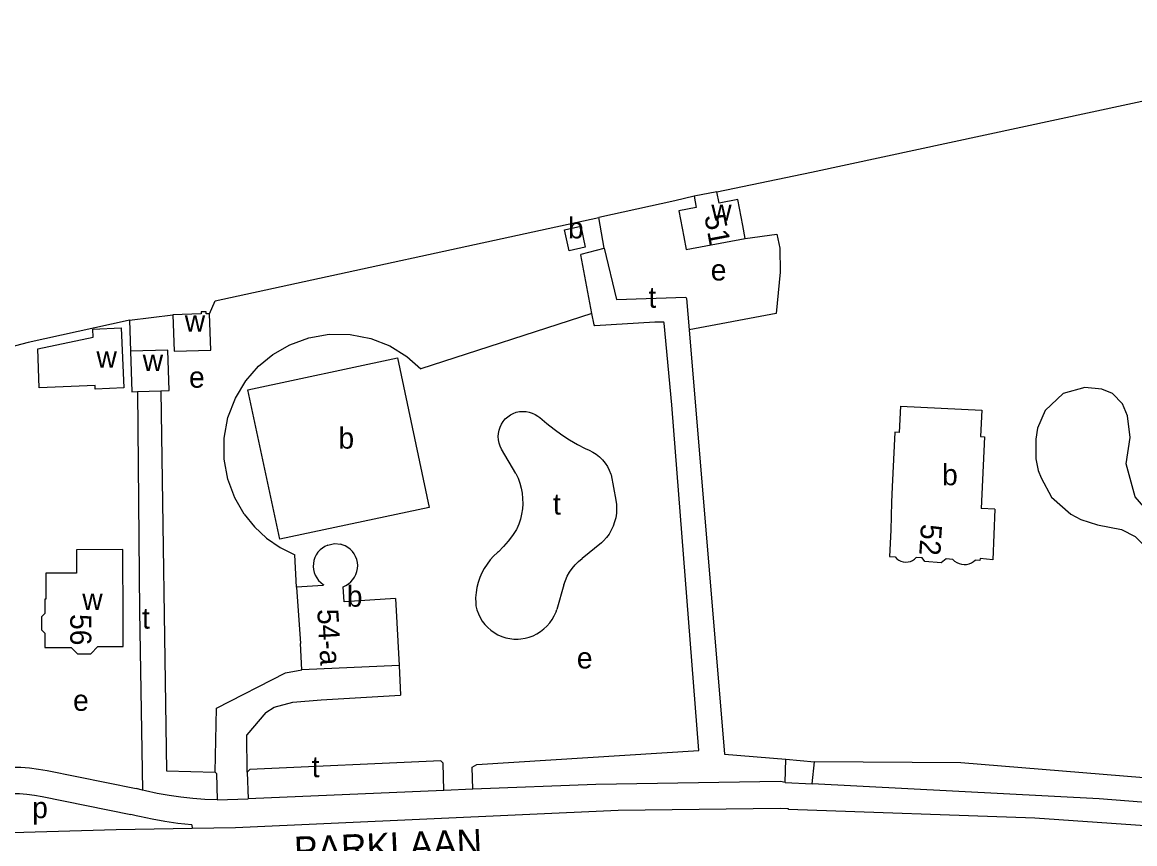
# Model space of a CAD drawing. Extents: x 161775 to 163181, y 382878 to 383925.
# Drawn here: x 161952.3 to 162163.3, y 383621.1 to 383777 of the extents above; entities that cross this region are included whole.
import ezdxf

# ---------------------------------------------------------------- set-up
doc = ezdxf.new("R2010")
doc.units = 0
for name, color, linetype in [('BLT_Basislijn', 7, 'Continuous'), ('BLT_Bebouwing', 7, 'Continuous'), ('BLT_Centroide', 7, 'Continuous'), ('BLT_Huisnummer', 7, 'Continuous'), ('BLT_Huisnummer_reeks', 7, 'Continuous'), ('BLT_Straatnaam', 7, 'Continuous')]:
    doc.layers.add(name, color=color, linetype=linetype)

msp = doc.modelspace()

# ---------------------------------------------------------------- linework, layer by layer
at = {"layer": 'BLT_Basislijn'}
for p, q in [((162084.08, 383744.78), (162102.02, 383748.52)), ((162062.72, 383734.11), (162061.69, 383739.92)), ((161972.7, 383720.42), (161980.91, 383721.44)), ((161972.7, 383720.42), (161972.84, 383714.54)), ((162060.39, 383721.72), (162027.96, 383711.22)), ((162095.3, 383721.67), (162078.84, 383718.61)), ((162045.97, 383691.34), (162043.25, 383695.99)), ((162064.01, 383691.09), (162064.93, 383686.3)), ((162062.18, 383678.16), (162058.52, 383675.21)), ((162004.33, 383669.8), (162004.01, 383675.93)), ((162055.06, 383670.23), (162053.74, 383665.54)), ((162023.8, 383654.88), (162024.05, 383649.27)), ((162000.09, 383647.01), (162003.63, 383647.96)), ((162003.63, 383647.96), (162009.02, 383648.4)), ((162009.02, 383648.4), (162024.05, 383649.27)), ((161998.54, 383645.99), (161994.94, 383641.76)), ((161998.54, 383645.99), (162000.09, 383647.01)), ((161995, 383634.68), (161994.94, 383641.76)), ((162097.05, 383632.73), (162097.18, 383637.12)), ((162097.18, 383637.12), (162102.58, 383636.62)), ((162102.16, 383632.48), (162102.58, 383636.62)), ((161957.05, 383634.98), (161973.91, 383631.58)), ((161975.16, 383631.26), (161973.91, 383631.58)), ((162032.32, 383631.2), (161995.16, 383629.58)), ((162037.8, 383631.47), (162032.32, 383631.2)), ((162097.05, 383632.73), (162102.16, 383632.48)), ((161956.13, 383630.06), (161972.92, 383626.67)), ((161989.27, 383629.43), (161995.16, 383629.58)), ((161973.96, 383626.41), (161972.92, 383626.67)), ((161984.52, 383624.67), (161984.53, 383623.99))]:
    msp.add_line(p, q, dxfattribs=at)
for points in [[(162102.02, 383748.52), (162181.43, 383765.6), (162207.15, 383772.92), (162219.96, 383776.97)], [(162079.78, 383743.97), (162076.13, 383743.06), (162061.69, 383739.92)], [(161987.86, 383721.65), (161988.93, 383724.12), (162061.69, 383739.92)], [(162089.44, 383735.94), (162095.45, 383736.78), (162096.04, 383734.08), (162096.08, 383729.57), (162095.3, 383721.67)], [(162060.39, 383721.72), (162058.3, 383732.81), (162058.35, 383732.97), (162062.72, 383734.11)], [(162062.72, 383734.11), (162065.06, 383724.33), (162078.19, 383724.78), (162078.35, 383724.56), (162078.84, 383718.61)], [(161972.7, 383720.42), (161972.4, 383720.39), (161953.48, 383716.22), (161914.12, 383705.92), (161900, 383701.78), (161882.86, 383696.55)], [(162037.8, 383631.47), (162037.69, 383635.6), (162038.53, 383636.13), (162080.66, 383638.81), (162075.54, 383704.37), (162074.08, 383719.89), (162074.01, 383720.08), (162072.29, 383720.08), (162060.96, 383719.38), (162060.8, 383719.54), (162060.39, 383721.72)], [(161994.43, 383683.62), (161992.64, 383686.71), (161991.33, 383690.24), (161990.62, 383694.07), (161990.62, 383698.05), (161991.35, 383701.97), (161992.76, 383705.66), (161994.74, 383708.94), (161997.16, 383711.7), (161999.88, 383713.94), (162003.06, 383715.78), (162006.66, 383717.09), (162010.54, 383717.77), (162014.54, 383717.73), (162018.44, 383716.96), (162022.06, 383715.54), (162025.27, 383713.57), (162027.96, 383711.22)], [(162078.84, 383718.61), (162085.51, 383638.09), (162097.18, 383637.12)], [(161978.59, 383707.03), (161979.67, 383634.9), (161988.89, 383634.7)], [(162169.13, 383680.34), (162163.39, 383686.91), (162161.7, 383693.18), (162162.49, 383698.2), (162161.98, 383702.31), (162161, 383704.58), (162159.09, 383706.49), (162157.08, 383707.35), (162153.9, 383707.67), (162149.76, 383706.55), (162146.32, 383703.31), (162144.87, 383699.97), (162144.59, 383697.88), (162144.59, 383694.14), (162145.03, 383691.88), (162145.56, 383690.51), (162147.53, 383686.82), (162151.19, 383683.64), (162153.1, 383682.64), (162156.29, 383681.62), (162160.84, 383680.7), (162163.39, 383679.4), (162165.31, 383677.52), (162166.85, 383674.82)], [(161974.19, 383706.88), (161974.54, 383665.2), (161975.16, 383631.26)], [(162043.25, 383695.99), (162042.98, 383696.54), (162042.77, 383697.12), (162042.65, 383697.73), (162042.61, 383698.34), (162042.64, 383698.96), (162042.76, 383699.56), (162042.95, 383700.15), (162043.21, 383700.7), (162043.55, 383701.22), (162043.95, 383701.69), (162044.41, 383702.1), (162044.92, 383702.46), (162045.46, 383702.74), (162046.04, 383702.95), (162046.65, 383703.08), (162047.26, 383703.13), (162047.88, 383703.11), (162048.49, 383703), (162049.07, 383702.82), (162049.63, 383702.56), (162050.15, 383702.23), (162050.48, 383701.97)], [(162050.48, 383701.97), (162051.82, 383700.82), (162053.21, 383699.73), (162054.65, 383698.7), (162056.13, 383697.74), (162057.66, 383696.85), (162059.13, 383696.07)], [(162059.13, 383696.07), (162059.86, 383695.78), (162060.56, 383695.42), (162061.21, 383694.99), (162061.82, 383694.49), (162062.38, 383693.94), (162062.87, 383693.33), (162063.31, 383692.67), (162063.67, 383691.98), (162063.96, 383691.24), (162064.01, 383691.09)], [(162045.97, 383691.34), (162046.38, 383690.44), (162046.71, 383689.51), (162046.96, 383688.55), (162047.14, 383687.58), (162047.24, 383686.6), (162047.25, 383685.61), (162047.19, 383684.62), (162047.05, 383683.64), (162046.83, 383682.68), (162046.53, 383681.74), (162046.16, 383680.82), (162046.1, 383680.71)], [(162064.93, 383686.3), (162065.04, 383685.47), (162065.07, 383684.63), (162065.02, 383683.79), (162064.9, 383682.95), (162064.69, 383682.14), (162064.41, 383681.35), (162064.05, 383680.58), (162063.62, 383679.86), (162063.13, 383679.17), (162062.57, 383678.54), (162062.18, 383678.16)], [(161994.43, 383683.62), (161996.38, 383681.21), (161998.67, 383679.08), (162001.24, 383677.31), (162004.01, 383675.93)], [(162046.1, 383680.71), (162045.33, 383679.58), (162044.49, 383678.51), (162043.59, 383677.48), (162042.63, 383676.51), (162042.44, 383676.33)], [(162042.44, 383676.33), (162041.73, 383675.66), (162041.08, 383674.94), (162040.48, 383674.16), (162039.96, 383673.34), (162039.5, 383672.48), (162039.11, 383671.58), (162038.8, 383670.65), (162038.57, 383669.7), (162038.41, 383668.74), (162038.33, 383667.77), (162038.34, 383666.79), (162038.37, 383666.26)], [(162055.06, 383670.23), (162055.34, 383671.05), (162055.7, 383671.85), (162056.13, 383672.61), (162056.63, 383673.34), (162057.19, 383674.01), (162057.81, 383674.63), (162058.52, 383675.21)], [(162168.35, 383672.76), (162173.38, 383669.31), (162180.96, 383669.11), (162183.12, 383666.7), (162182.8, 383632.96), (162182.64, 383632.33), (162180.48, 383632.31), (162130.35, 383636.45), (162102.58, 383636.62)], [(162038.37, 383666.26), (162038.56, 383665.49), (162038.84, 383664.74), (162039.18, 383664.02), (162039.59, 383663.35), (162040.08, 383662.71), (162040.62, 383662.13), (162041.21, 383661.61), (162041.86, 383661.15), (162042.55, 383660.76), (162043.28, 383660.43), (162044.03, 383660.18), (162044.81, 383660.02), (162045.6, 383659.92), (162046.39, 383659.91), (162046.92, 383659.95)], [(162046.92, 383659.95), (162047.71, 383660.08), (162048.49, 383660.28), (162049.24, 383660.56), (162049.96, 383660.92), (162050.64, 383661.34), (162051.28, 383661.84), (162051.86, 383662.39), (162052.39, 383662.99), (162052.85, 383663.65), (162053.25, 383664.35), (162053.58, 383665.09), (162053.74, 383665.54)], [(161988.89, 383634.7), (161989.15, 383646.84), (162002.26, 383653.54), (162005.37, 383654.06)], [(161950.34, 383635.64), (161952.05, 383635.59), (161953.72, 383635.47), (161955.39, 383635.26), (161957.05, 383634.98)], [(162032.32, 383631.2), (162032.15, 383636.37), (162031.74, 383636.8), (161995.48, 383635.18), (161995, 383634.68)], [(161988.89, 383634.7), (161989.15, 383634.43), (161989.27, 383629.43)], [(161995, 383634.68), (161995.16, 383629.58)], [(161989.27, 383629.43), (161986.98, 383629.51), (161984.7, 383629.68), (161982.43, 383629.93), (161980.17, 383630.25), (161977.92, 383630.65), (161975.68, 383631.13), (161975.16, 383631.26)], [(162097.05, 383632.73), (162096.16, 383632.87), (162061.12, 383632.31), (162037.8, 383631.47)], [(162187.15, 383627.23), (162156.61, 383629.61), (162102.16, 383632.48)], [(161950.21, 383630.64), (161951.79, 383630.6), (161953.23, 383630.49), (161954.66, 383630.32), (161956.13, 383630.06)], [(162190.28, 383626.87), (162185.31, 383623.07), (162144.41, 383625.95), (162097.66, 383627.58), (162097.66, 383627.74), (162096.06, 383627.77), (162065.35, 383627.38), (161992.75, 383624.13)], [(161984.52, 383624.67), (161981.81, 383624.96), (161979.37, 383625.31), (161976.95, 383625.75), (161974.55, 383626.26), (161973.96, 383626.41)], [(161984.53, 383623.99), (161970.12, 383623.75), (161950.39, 383623.19)], [(161992.75, 383624.13), (161984.53, 383623.99)]]:
    msp.add_lwpolyline(points, dxfattribs=at)
at = {"layer": 'BLT_Bebouwing'}
for p, q in [((162084.08, 383744.78), (162079.78, 383743.97)), ((161974.19, 383706.88), (161978.59, 383707.03)), ((162136.8, 383684.56), (162134.2, 383684.69)), ((162009.45, 383670.26), (162009.38, 383670.08)), ((162023.11, 383667.63), (162023.8, 383654.88))]:
    msp.add_line(p, q, dxfattribs=at)
for points in [[(162079.78, 383743.97), (162080.18, 383741.83), (162076.86, 383741.21), (162077.79, 383736.24), (162078.24, 383733.84), (162089.44, 383735.94)], [(162089.44, 383735.94), (162088.98, 383738.4), (162088.06, 383743.31), (162084.49, 383742.64), (162084.08, 383744.78)], [(162055.21, 383737.6), (162058.26, 383738.28), (162059.12, 383734.27), (162056.08, 383733.59), (162055.21, 383737.6)], [(161987.86, 383721.65), (161987.2, 383721.62), (161987.19, 383722.03), (161986.25, 383721.99), (161986.27, 383721.61), (161980.91, 383721.44)], [(161980.91, 383721.44), (161981.14, 383714.53)], [(161981.14, 383714.53), (161988.08, 383714.76), (161987.86, 383721.65)], [(161979.93, 383714.77), (161972.84, 383714.54)], [(161972.84, 383714.54), (161973.09, 383706.85), (161974.19, 383706.88)], [(161978.59, 383707.03), (161980.18, 383707.08), (161979.93, 383714.77)], [(161995.12, 383707.23), (162023.48, 383713.26), (162029.5, 383684.91), (162001.16, 383678.88), (161995.12, 383707.23)], [(162118.88, 383704.11), (162118.64, 383699.12), (162117.84, 383699.16), (162117.33, 383688.84), (162117.19, 383685.91), (162117.05, 383680.61), (162116.8, 383675.61), (162117.9, 383675.52)], [(162118.88, 383704.11), (162134.31, 383703.36), (162134.07, 383698.36), (162134.87, 383698.33), (162134.2, 383684.69)], [(162136.8, 383684.56), (162136.42, 383674.98), (162134.01, 383675.19), (162133.98, 383674.83), (162133.09, 383674.91)], [(162010.28, 383677.75), (162009.75, 383677.51), (162009.26, 383677.2), (162008.81, 383676.83), (162008.42, 383676.4), (162008.1, 383675.92), (162007.84, 383675.41), (162007.65, 383674.86), (162007.55, 383674.29), (162007.52, 383673.71), (162007.57, 383673.13), (162007.7, 383672.56), (162007.91, 383672.02), (162008.19, 383671.52), (162008.54, 383671.05), (162008.95, 383670.64), (162009.41, 383670.29), (162009.45, 383670.26)], [(162010.28, 383677.75), (162011.54, 383678.03), (162012.76, 383677.91)], [(162013.19, 383669.86), (162013.72, 383670.1), (162014.21, 383670.4), (162014.65, 383670.78), (162015.04, 383671.21), (162015.37, 383671.68), (162015.63, 383672.2), (162015.82, 383672.75), (162015.92, 383673.32), (162015.95, 383673.9), (162015.9, 383674.48), (162015.77, 383675.05), (162015.56, 383675.59), (162015.28, 383676.1), (162014.94, 383676.56), (162014.53, 383676.98), (162014.07, 383677.33), (162013.57, 383677.62), (162013.03, 383677.83), (162012.76, 383677.91)], [(161971.46, 383663.51), (161971.43, 383676.9), (161962.61, 383676.88), (161962.62, 383672.43), (161956.81, 383672.41), (161956.82, 383667.49), (161956.61, 383667.49), (161956.61, 383664.76), (161955.98, 383664.12), (161955.98, 383661.7), (161956.64, 383661.05), (161956.64, 383658.32), (161961.6, 383658.34), (161962.81, 383657.13), (161965.31, 383657.14), (161966.66, 383658.49), (161971.47, 383658.51), (161971.46, 383663.51)], [(162117.9, 383675.52), (162118.22, 383675.18), (162118.59, 383674.91), (162119, 383674.71), (162119.43, 383674.58), (162119.89, 383674.53), (162120.35, 383674.56), (162120.79, 383674.67), (162121.21, 383674.85), (162121.59, 383675.1), (162121.91, 383675.4)], [(162128.82, 383675.05), (162127.58, 383675.16), (162126.65, 383674.38), (162123.53, 383674.66), (162122.99, 383675.31), (162121.91, 383675.4)], [(162128.82, 383675.05), (162129.17, 383674.71), (162129.57, 383674.44), (162130.01, 383674.24), (162130.48, 383674.11), (162130.96, 383674.06), (162131.45, 383674.09), (162131.92, 383674.2), (162132.37, 383674.39), (162132.78, 383674.64), (162133.09, 383674.91)], [(162009.38, 383670.08), (162004.33, 383669.8)], [(162004.33, 383669.8), (162005.08, 383659.06)], [(162023.11, 383667.63), (162013.37, 383667.01), (162013.19, 383669.86)], [(162005.37, 383654.06), (162005.08, 383659.06)], [(162023.8, 383654.88), (162005.37, 383654.06)]]:
    msp.add_lwpolyline(points, dxfattribs=at)
msp.add_lwpolyline([(161965.72, 383718.75), (161971.1, 383718.97), (161971.59, 383707.58), (161966.19, 383707.35), (161966.16, 383708.02), (161955.54, 383707.58), (161955.29, 383714.97), (161965.77, 383717.21)], close=True, dxfattribs=at)

# ---------------------------------------------------------------- texts
at = {"layer": 'BLT_Centroide'}
for s, p in [('w', (162083.02, 383739.31)), ('b', (162055.84, 383735.94)), ('e', (162082.92, 383727.96)), ('t', (162071.1, 383722.79)), ('w', (161983.16, 383718.28)), ('w', (161966.41, 383711.42)), ('w', (161975.18, 383710.81)), ('e', (161983.96, 383707.62)), ('b', (162012.31, 383696.06)), ('b', (162126.8, 383689.11)), ('t', (162053, 383683.54)), ('b', (162013.89, 383666.06)), ('w', (161963.72, 383665.47)), ('t', (161975.05, 383661.9)), ('e', (162057.52, 383654.35)), ('e', (161961.97, 383646.3)), ('t', (162007.23, 383633.72)), ('p', (161954.22, 383625.94))]:
    msp.add_text(s, height=4, dxfattribs=at).set_placement(p)
at = {"layer": 'BLT_Huisnummer'}
for s, rotation, p in [('51', 280.6267, (162081.68, 383740.18)), ('52', 266.549, (162122.81, 383681.84)), ('56', 270.1261, (161961.43, 383664.67))]:
    msp.add_text(s, height=4, rotation=rotation, dxfattribs=at).set_placement(p)
at = {"layer": 'BLT_Huisnummer_reeks'}
msp.add_text('54-a', height=4, rotation=273.279, dxfattribs=at).set_placement((162008.27, 383665.55))
at = {"layer": 'BLT_Straatnaam'}
msp.add_text('PARKLAAN', height=5, rotation=2.4537, dxfattribs=at).set_placement((162004, 383617.42))

doc.saveas('drawing.dxf')
